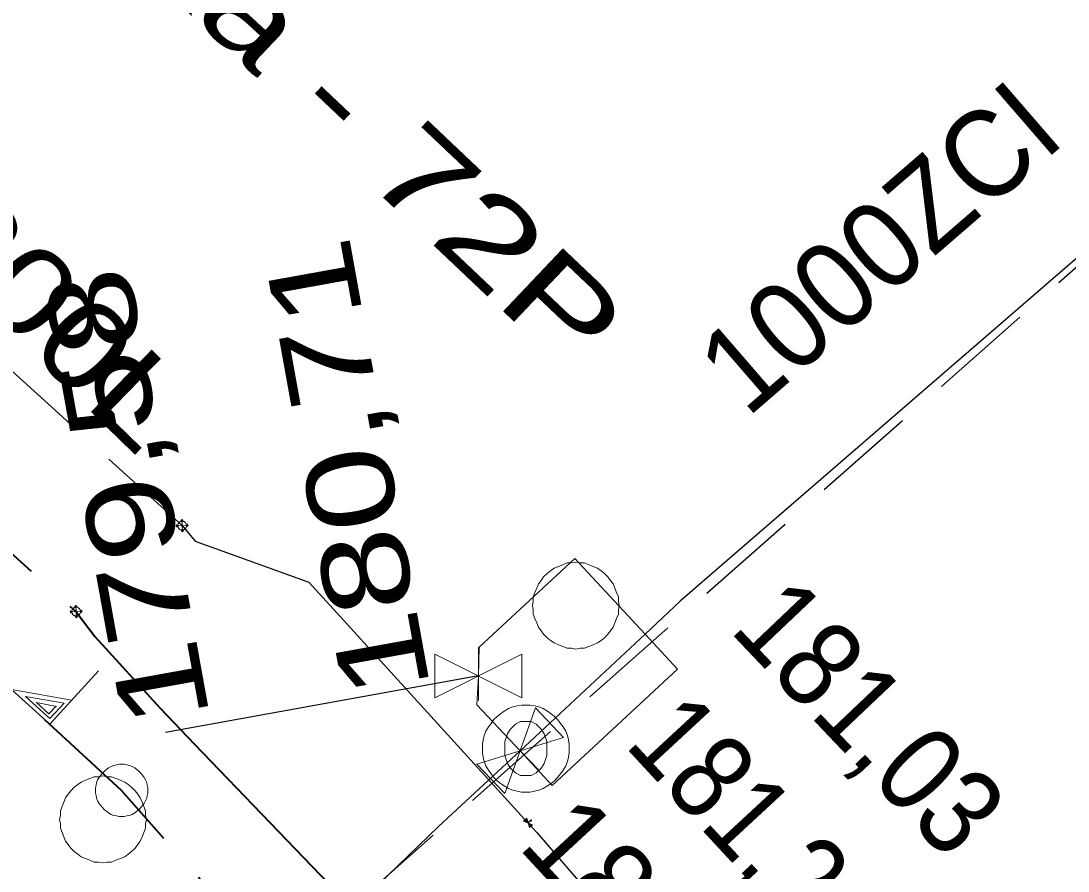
# Model space of a CAD drawing. Extents: x -740851 to -738888, y -1041382 to -1040235.
# Drawn here: x -739704.31 to -739692.27, y -1040571.08 to -1040561.3 of the extents above; entities that cross this region are included whole.
import ezdxf

# ---------------------------------------------------------------- set-up
doc = ezdxf.new("R2010")
doc.units = 0
doc.header["$LTSCALE"] = 0.4
doc.linetypes.add('MEDIUM_DASHED', pattern=[4.5, 3, -1.5])
for name, color, linetype, lineweight in [('18', 7, 'Continuous', 13), ('20', 7, 'MEDIUM_DASHED', 25), ('8', 7, 'Continuous', 13)]:
    doc.layers.add(name, color=color, linetype=linetype, lineweight=lineweight)

msp = doc.modelspace()

# ---------------------------------------------------------------- linework, layer by layer
at = {"layer": '18', "linetype": 'MEDIUM_DASHED', "lineweight": 40}
msp.add_line((-739703.155, -1040570.156), (-739713.989, -1040560.24), dxfattribs=at)
at = {"layer": '18', "lineweight": 25}
for p, q in [((-739696.73, -1040567.98), (-739697.13, -1040568.36)), ((-739699.05, -1040568.84), (-739702.65, -1040569.49)), ((-739698.57, -1040569.7), (-739699.51, -1040570.57)), ((-739699.51, -1040570.57), (-739701.28, -1040572.28))]:
    msp.add_line(p, q, dxfattribs=at)
at = {"layer": '18'}
for p, q in [((-739699.05, -1040568.84), (-739699.05, -1040568.51)), ((-739699.05, -1040568.84), (-739699.05, -1040569.12)), ((-739698.57, -1040569.7), (-739698.751, -1040569.51)), ((-739698.57, -1040569.7), (-739698.357, -1040569.924))]:
    msp.add_line(p, q, dxfattribs=at)
at = {"layer": '18', "lineweight": 25}
msp.add_lwpolyline([(-739659.45, -1040534.92), (-739688.27, -1040560.66), (-739696.73, -1040567.98)], dxfattribs=at)
at = {"layer": '18'}
for points in [[(-739699.04, -1040568.51), (-739697.94, -1040567.49), (-739697.13, -1040568.36), (-739696.76, -1040568.76), (-739698.2, -1040570.1), (-739698.57, -1040569.7), (-739699.07, -1040569.17), (-739699.05, -1040568.84)], [(-739697.43, -1040568.03), (-739697.44, -1040567.98), (-739697.44, -1040567.93), (-739697.46, -1040567.88), (-739697.48, -1040567.83), (-739697.5, -1040567.78), (-739697.53, -1040567.74), (-739697.56, -1040567.7), (-739697.6, -1040567.66), (-739697.64, -1040567.63), (-739697.68, -1040567.6), (-739697.73, -1040567.58), (-739697.78, -1040567.56), (-739697.83, -1040567.54), (-739697.88, -1040567.54), (-739697.93, -1040567.53), (-739697.98, -1040567.54), (-739698.03, -1040567.54), (-739698.08, -1040567.56), (-739698.13, -1040567.58), (-739698.18, -1040567.6), (-739698.22, -1040567.63), (-739698.26, -1040567.66), (-739698.3, -1040567.7), (-739698.33, -1040567.74), (-739698.36, -1040567.78), (-739698.38, -1040567.83), (-739698.4, -1040567.88), (-739698.42, -1040567.93), (-739698.42, -1040567.98), (-739698.43, -1040568.03), (-739698.42, -1040568.08), (-739698.42, -1040568.13), (-739698.4, -1040568.18), (-739698.38, -1040568.23), (-739698.36, -1040568.28), (-739698.33, -1040568.32), (-739698.3, -1040568.36), (-739698.26, -1040568.4), (-739698.22, -1040568.43), (-739698.18, -1040568.46), (-739698.13, -1040568.48), (-739698.08, -1040568.5), (-739698.03, -1040568.52), (-739697.98, -1040568.52), (-739697.93, -1040568.53), (-739697.88, -1040568.52), (-739697.83, -1040568.52), (-739697.78, -1040568.5), (-739697.73, -1040568.48), (-739697.68, -1040568.46), (-739697.64, -1040568.43), (-739697.6, -1040568.4), (-739697.56, -1040568.36), (-739697.53, -1040568.32), (-739697.5, -1040568.28), (-739697.48, -1040568.23), (-739697.46, -1040568.18), (-739697.44, -1040568.13), (-739697.44, -1040568.08)], [(-739699.55, -1040568.59), (-739698.55, -1040569.09), (-739698.55, -1040568.59), (-739699.55, -1040569.09)], [(-739698.07, -1040569.547), (-739699.07, -1040569.853), (-739698.748, -1040570.192), (-739698.392, -1040569.208)], [(-739698.005, -1040569.675), (-739698.005, -1040569.625), (-739698.015, -1040569.575), (-739698.025, -1040569.525), (-739698.045, -1040569.475), (-739698.075, -1040569.425), (-739698.105, -1040569.385), (-739698.135, -1040569.345), (-739698.175, -1040569.305), (-739698.215, -1040569.275), (-739698.255, -1040569.245), (-739698.305, -1040569.215), (-739698.355, -1040569.195), (-739698.405, -1040569.185), (-739698.455, -1040569.175), (-739698.505, -1040569.175), (-739698.555, -1040569.175), (-739698.605, -1040569.185), (-739698.655, -1040569.195), (-739698.705, -1040569.215), (-739698.755, -1040569.245), (-739698.795, -1040569.275), (-739698.835, -1040569.305), (-739698.875, -1040569.345), (-739698.905, -1040569.385), (-739698.935, -1040569.425), (-739698.965, -1040569.475), (-739698.985, -1040569.525), (-739698.995, -1040569.575), (-739699.005, -1040569.625), (-739699.005, -1040569.675), (-739699.005, -1040569.725), (-739698.995, -1040569.775), (-739698.985, -1040569.825), (-739698.965, -1040569.875), (-739698.935, -1040569.925), (-739698.905, -1040569.965), (-739698.875, -1040570.005), (-739698.835, -1040570.045), (-739698.795, -1040570.075), (-739698.755, -1040570.105), (-739698.705, -1040570.135), (-739698.655, -1040570.155), (-739698.605, -1040570.165), (-739698.555, -1040570.175), (-739698.505, -1040570.175), (-739698.455, -1040570.175), (-739698.405, -1040570.165), (-739698.355, -1040570.155), (-739698.305, -1040570.135), (-739698.255, -1040570.105), (-739698.215, -1040570.075), (-739698.175, -1040570.045), (-739698.135, -1040570.005), (-739698.105, -1040569.965), (-739698.075, -1040569.925), (-739698.045, -1040569.875), (-739698.025, -1040569.825), (-739698.015, -1040569.775), (-739698.005, -1040569.725)], [(-739698.565, -1040569.365), (-739698.625, -1040569.395), (-739698.685, -1040569.455), (-739698.715, -1040569.505), (-739698.745, -1040569.595), (-739698.745, -1040569.755), (-739698.715, -1040569.845), (-739698.685, -1040569.895), (-739698.625, -1040569.955), (-739698.565, -1040569.985), (-739698.445, -1040569.985), (-739698.385, -1040569.955), (-739698.325, -1040569.895), (-739698.295, -1040569.845), (-739698.265, -1040569.755), (-739698.265, -1040569.595), (-739698.295, -1040569.505), (-739698.325, -1040569.455), (-739698.385, -1040569.395), (-739698.445, -1040569.365)], [(-739702.855, -1040570.156), (-739702.855, -1040570.126), (-739702.861, -1040570.096), (-739702.867, -1040570.066), (-739702.879, -1040570.036), (-739702.897, -1040570.006), (-739702.915, -1040569.982), (-739702.933, -1040569.958), (-739702.957, -1040569.934), (-739702.981, -1040569.916), (-739703.005, -1040569.898), (-739703.035, -1040569.88), (-739703.065, -1040569.868), (-739703.095, -1040569.862), (-739703.125, -1040569.856), (-739703.155, -1040569.856), (-739703.185, -1040569.856), (-739703.215, -1040569.862), (-739703.245, -1040569.868), (-739703.275, -1040569.88), (-739703.305, -1040569.898), (-739703.329, -1040569.916), (-739703.353, -1040569.934), (-739703.377, -1040569.958), (-739703.395, -1040569.982), (-739703.413, -1040570.006), (-739703.431, -1040570.036), (-739703.443, -1040570.066), (-739703.449, -1040570.096), (-739703.455, -1040570.126), (-739703.455, -1040570.156), (-739703.455, -1040570.186), (-739703.449, -1040570.216), (-739703.443, -1040570.246), (-739703.431, -1040570.276), (-739703.413, -1040570.306), (-739703.395, -1040570.33), (-739703.377, -1040570.354), (-739703.353, -1040570.378), (-739703.329, -1040570.396), (-739703.305, -1040570.414), (-739703.275, -1040570.432), (-739703.245, -1040570.444), (-739703.215, -1040570.45), (-739703.185, -1040570.456), (-739703.155, -1040570.456), (-739703.125, -1040570.456), (-739703.095, -1040570.45), (-739703.065, -1040570.444), (-739703.035, -1040570.432), (-739703.005, -1040570.414), (-739702.981, -1040570.396), (-739702.957, -1040570.378), (-739702.933, -1040570.354), (-739702.915, -1040570.33), (-739702.897, -1040570.306), (-739702.879, -1040570.276), (-739702.867, -1040570.246), (-739702.861, -1040570.216), (-739702.855, -1040570.186)], [(-739702.87, -1040570.49), (-739702.88, -1040570.44), (-739702.88, -1040570.39), (-739702.9, -1040570.34), (-739702.92, -1040570.29), (-739702.94, -1040570.24), (-739702.97, -1040570.2), (-739703, -1040570.16), (-739703.04, -1040570.12), (-739703.08, -1040570.09), (-739703.12, -1040570.06), (-739703.17, -1040570.04), (-739703.22, -1040570.02), (-739703.27, -1040570), (-739703.32, -1040570), (-739703.37, -1040569.99), (-739703.42, -1040570), (-739703.47, -1040570), (-739703.52, -1040570.02), (-739703.57, -1040570.04), (-739703.62, -1040570.06), (-739703.66, -1040570.09), (-739703.7, -1040570.12), (-739703.74, -1040570.16), (-739703.77, -1040570.2), (-739703.8, -1040570.24), (-739703.82, -1040570.29), (-739703.84, -1040570.34), (-739703.86, -1040570.39), (-739703.86, -1040570.44), (-739703.87, -1040570.49), (-739703.86, -1040570.54), (-739703.86, -1040570.59), (-739703.84, -1040570.64), (-739703.82, -1040570.69), (-739703.8, -1040570.74), (-739703.77, -1040570.78), (-739703.74, -1040570.82), (-739703.7, -1040570.86), (-739703.66, -1040570.89), (-739703.62, -1040570.92), (-739703.57, -1040570.94), (-739703.52, -1040570.96), (-739703.47, -1040570.98), (-739703.42, -1040570.98), (-739703.37, -1040570.99), (-739703.32, -1040570.98), (-739703.27, -1040570.98), (-739703.22, -1040570.96), (-739703.17, -1040570.94), (-739703.12, -1040570.92), (-739703.08, -1040570.89), (-739703.04, -1040570.86), (-739703, -1040570.82), (-739702.97, -1040570.78), (-739702.94, -1040570.74), (-739702.92, -1040570.69), (-739702.9, -1040570.64), (-739702.88, -1040570.59), (-739702.88, -1040570.54)]]:
    msp.add_lwpolyline(points, close=True, dxfattribs=at)
for points in [[(-739703.421, -1040568.782), (-739703.983, -1040569.396), (-739704.421, -1040568.995), (-739703.729, -1040569.119)], [(-739703.818, -1040569.151), (-739703.981, -1040569.33), (-739704.261, -1040569.074), (-739703.815, -1040569.154)], [(-739703.909, -1040569.186), (-739703.991, -1040569.276), (-739704.134, -1040569.144), (-739703.906, -1040569.189)]]:
    msp.add_lwpolyline(points, dxfattribs=at)
at = {"layer": '18', "linetype": 'MEDIUM_DASHED', "lineweight": 40}
msp.add_lwpolyline([(-739669.06, -1040610.98), (-739674.7, -1040603.39), (-739681.24, -1040595.01), (-739703.155, -1040570.156)], dxfattribs=at)
at = {"layer": '20', "linetype": 'Continuous'}
msp.add_line((-739697.13, -1040568.36), (-739698.57, -1040569.7), dxfattribs=at)
at = {"layer": '20'}
msp.add_lwpolyline([(-739674.14, -1040548.21), (-739688.774, -1040561.14), (-739702.73, -1040573.46)], dxfattribs=at)
at = {"layer": '8', "linetype": 'MEDIUM_DASHED', "lineweight": 25}
msp.add_line((-739709.965, -1040560.292), (-739702.46, -1040567.11), dxfattribs=at)
at = {"layer": '8'}
for p, q in [((-739702.529, -1040567.113), (-739702.516, -1040567.099)), ((-739702.529, -1040567.113), (-739702.388, -1040567.107)), ((-739702.529, -1040567.113), (-739702.514, -1040567.127)), ((-739702.462, -1040567.039), (-739702.475, -1040567.054)), ((-739702.462, -1040567.039), (-739702.455, -1040567.181)), ((-739702.462, -1040567.039), (-739702.447, -1040567.053)), ((-739702.388, -1040567.107), (-739702.403, -1040567.093)), ((-739702.388, -1040567.107), (-739702.401, -1040567.121)), ((-739702.455, -1040567.181), (-739702.47, -1040567.167)), ((-739702.455, -1040567.181), (-739702.442, -1040567.166)), ((-739703.749, -1040568.103), (-739703.736, -1040568.088)), ((-739703.682, -1040568.029), (-739703.696, -1040568.044)), ((-739703.682, -1040568.029), (-739703.675, -1040568.17)), ((-739703.682, -1040568.029), (-739703.667, -1040568.042)), ((-739703.608, -1040568.096), (-739703.623, -1040568.083)), ((-739703.749, -1040568.103), (-739703.608, -1040568.096)), ((-739703.749, -1040568.103), (-739703.734, -1040568.117)), ((-739703.675, -1040568.17), (-739703.69, -1040568.157)), ((-739703.675, -1040568.17), (-739703.661, -1040568.155)), ((-739703.608, -1040568.096), (-739703.621, -1040568.111)), ((-739698.478, -1040570.53), (-739698.441, -1040570.496))]:
    msp.add_line(p, q, dxfattribs=at)
at = {"layer": '8', "linetype": 'MEDIUM_DASHED', "lineweight": 40}
msp.add_lwpolyline([(-739800.406, -1040510.509), (-739783.874, -1040510.33), (-739769.682, -1040516.575), (-739747.937, -1040528.604), (-739744.345, -1040531.012), (-739722.292, -1040550.654), (-739710.435, -1040562.012), (-739703.68, -1040568.1)], dxfattribs=at)
at = {"layer": '8'}
for points in [[(-739702.421, -1040567.144), (-739702.418, -1040567.14), (-739702.415, -1040567.136), (-739702.413, -1040567.131), (-739702.411, -1040567.126), (-739702.41, -1040567.12), (-739702.409, -1040567.115), (-739702.409, -1040567.11), (-739702.409, -1040567.105), (-739702.41, -1040567.1), (-739702.411, -1040567.095), (-739702.413, -1040567.089), (-739702.415, -1040567.085), (-739702.418, -1040567.08), (-739702.421, -1040567.076), (-739702.425, -1040567.073), (-739702.429, -1040567.07), (-739702.433, -1040567.067), (-739702.437, -1040567.064), (-739702.442, -1040567.063), (-739702.448, -1040567.061), (-739702.453, -1040567.061), (-739702.458, -1040567.06), (-739702.464, -1040567.061), (-739702.469, -1040567.062), (-739702.474, -1040567.063), (-739702.479, -1040567.064), (-739702.484, -1040567.067), (-739702.488, -1040567.07), (-739702.492, -1040567.073), (-739702.495, -1040567.076), (-739702.499, -1040567.08), (-739702.501, -1040567.084), (-739702.504, -1040567.089), (-739702.506, -1040567.094), (-739702.507, -1040567.1), (-739702.508, -1040567.105), (-739702.508, -1040567.11), (-739702.508, -1040567.115), (-739702.507, -1040567.12), (-739702.506, -1040567.125), (-739702.504, -1040567.131), (-739702.502, -1040567.135), (-739702.499, -1040567.14), (-739702.496, -1040567.144), (-739702.492, -1040567.147), (-739702.488, -1040567.15), (-739702.484, -1040567.153), (-739702.48, -1040567.156), (-739702.475, -1040567.158), (-739702.469, -1040567.159), (-739702.464, -1040567.159), (-739702.459, -1040567.16), (-739702.453, -1040567.159), (-739702.448, -1040567.158), (-739702.443, -1040567.157), (-739702.438, -1040567.156), (-739702.433, -1040567.153), (-739702.429, -1040567.15), (-739702.425, -1040567.147)], [(-739703.641, -1040568.133), (-739703.638, -1040568.129), (-739703.635, -1040568.125), (-739703.633, -1040568.121), (-739703.631, -1040568.116), (-739703.63, -1040568.11), (-739703.629, -1040568.105), (-739703.629, -1040568.1), (-739703.629, -1040568.094), (-739703.63, -1040568.089), (-739703.631, -1040568.084), (-739703.633, -1040568.079), (-739703.635, -1040568.074), (-739703.638, -1040568.07), (-739703.641, -1040568.066), (-739703.645, -1040568.062), (-739703.649, -1040568.059), (-739703.653, -1040568.057), (-739703.657, -1040568.054), (-739703.663, -1040568.052), (-739703.668, -1040568.051), (-739703.673, -1040568.05), (-739703.678, -1040568.05), (-739703.684, -1040568.05), (-739703.689, -1040568.051), (-739703.694, -1040568.052), (-739703.699, -1040568.054), (-739703.704, -1040568.056), (-739703.708, -1040568.059), (-739703.712, -1040568.062), (-739703.716, -1040568.066), (-739703.719, -1040568.07), (-739703.722, -1040568.074), (-739703.724, -1040568.079), (-739703.726, -1040568.084), (-739703.727, -1040568.089), (-739703.728, -1040568.094), (-739703.728, -1040568.099), (-739703.728, -1040568.105), (-739703.727, -1040568.11), (-739703.726, -1040568.115), (-739703.724, -1040568.12), (-739703.722, -1040568.125), (-739703.719, -1040568.129), (-739703.716, -1040568.133), (-739703.712, -1040568.137), (-739703.708, -1040568.14), (-739703.704, -1040568.143), (-739703.699, -1040568.145), (-739703.694, -1040568.147), (-739703.689, -1040568.148), (-739703.684, -1040568.149), (-739703.679, -1040568.149), (-739703.673, -1040568.149), (-739703.668, -1040568.148), (-739703.663, -1040568.147), (-739703.658, -1040568.145), (-739703.653, -1040568.143), (-739703.649, -1040568.14), (-739703.645, -1040568.137)], [(-739698.53, -1040570.509), (-739698.427, -1040570.551), (-739698.463, -1040570.583), (-739698.494, -1040570.477)], [(-739698.525, -1040570.508), (-739698.482, -1040570.525), (-739698.496, -1040570.481)], [(-739698.522, -1040570.507), (-739698.497, -1040570.484), (-739698.486, -1040570.522)], [(-739698.518, -1040570.506), (-739698.498, -1040570.489), (-739698.49, -1040570.517)], [(-739698.513, -1040570.505), (-739698.5, -1040570.493), (-739698.493, -1040570.514)], [(-739698.51, -1040570.504), (-739698.501, -1040570.496), (-739698.497, -1040570.509)], [(-739698.505, -1040570.503), (-739698.502, -1040570.5), (-739698.501, -1040570.505)], [(-739698.431, -1040570.552), (-739698.461, -1040570.579), (-739698.474, -1040570.534)], [(-739698.46, -1040570.575), (-739698.435, -1040570.552), (-739698.471, -1040570.538)], [(-739698.458, -1040570.571), (-739698.439, -1040570.554), (-739698.467, -1040570.542)], [(-739698.457, -1040570.567), (-739698.443, -1040570.555), (-739698.464, -1040570.546)], [(-739698.456, -1040570.564), (-739698.447, -1040570.555), (-739698.46, -1040570.551)], [(-739698.454, -1040570.559), (-739698.451, -1040570.557), (-739698.456, -1040570.554)]]:
    msp.add_lwpolyline(points, close=True, dxfattribs=at)
at = {"layer": '8', "lineweight": 25}
for points in [[(-739702.46, -1040567.11), (-739702.31, -1040567.29), (-739701, -1040567.76), (-739700.6, -1040568.2), (-739698.48, -1040570.53)], [(-739698.48, -1040570.53), (-739698.38, -1040570.64), (-739697.88, -1040571.22), (-739697.55, -1040571.57), (-739697.27, -1040573.09), (-739696.48, -1040574)]]:
    msp.add_lwpolyline(points, dxfattribs=at)
at = {"layer": '8', "lineweight": 40}
msp.add_lwpolyline([(-739703.68, -1040568.1), (-739703.46, -1040568.39), (-739702.71, -1040569.21), (-739702.32, -1040569.62), (-739700.77, -1040571.23)], dxfattribs=at)
at = {"layer": '8'}
msp.add_lwpolyline([(-739698.458, -1040570.497), (-739698.441, -1040570.496), (-739698.442, -1040570.515)], dxfattribs=at)

# ---------------------------------------------------------------- texts
at = {"layer": '18'}
for s, rotation, width, p in [('OK 120E Povltavská - 72P', 316.536, 1.4, (-739714.059, -1040550.151)), ('1000ZCI', 40.868, 0.95, (-739695.959, -1040565.878)), ('180,71', 100.236, 1.3, (-739699.601, -1040568.979)), ('179,58', 100.234, 1.3, (-739702.137, -1040569.316)), ('181,03', 313.532, 0.9, (-739696.175, -1040568.317)), ('181,2', 312.786, 0.85, (-739697.38, -1040569.639)), ('180,88', 312.785, 0.95, (-739698.607, -1040570.806))]:
    msp.add_text(s, height=1, rotation=rotation, dxfattribs=dict(at, width=width)).set_placement(p)
at = {"layer": '8', "width": 1.2}
msp.add_text('300L', height=1, rotation=315.721, dxfattribs=at).set_placement((-739705.519, -1040563.84))

doc.saveas('drawing.dxf')
